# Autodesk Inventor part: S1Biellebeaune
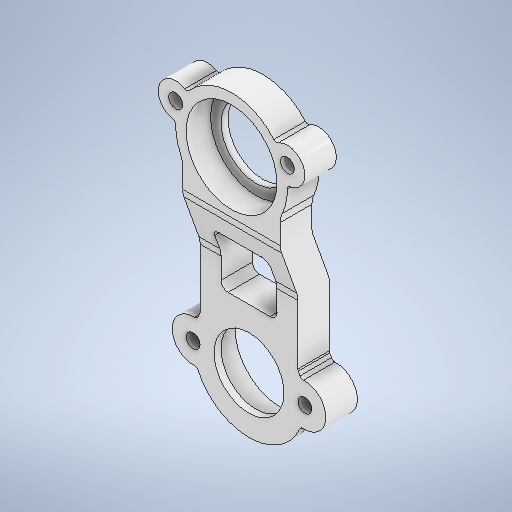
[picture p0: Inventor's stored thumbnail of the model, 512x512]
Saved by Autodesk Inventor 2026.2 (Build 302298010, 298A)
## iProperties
Created: 2026-04
Part Number: S1Biellebeaune
Material: Générique
Document SubType Name: Modeling
Designer: mel
Density: 1 g/cm^3
Appearance: Blanche
Author: mel
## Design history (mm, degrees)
sketch "Esquisse1"
  geometry: L1 (0, 0)-(-7.996, 2.998); L2 (0, -44.932)-(0, 17.591) reference; L3 (-7, -24)-(-7, -4.583); L4 (0, 0)-(7.996, 2.998); L5 (7, -24)-(7, -4.583); L6 (-3, -11.5)-(3, -11.5); L7 (4, -12.5)-(4, -18.5); L8 (3, -19.5)-(-3, -19.5); L9 (-4, -18.5)-(-4, -12.5); C1 r 1 at (-7.996, 2.998); C2 r 1 at (7.996, 2.998); C3 r 5 at (0, -28); C4 r 1 at (-8, -28); C5 r 1 at (8, -28); A1 r 2.5 centre (-7.996, 2.998) between (-6.692, 5.131) and (-8.416, 0.534); A2 r 0.5 centre (-6.431, 5.558) between (-6.692, 5.131) and (-6.053, 5.231); A3 r 0.5 centre (-8.5, 0.041) between (-8, 0.039) and (-8.416, 0.534); A4 r 5 centre (0, 0) between (0, 5) and (0, -5); A5 r 3 centre (-10, -4.583) between (-7, -4.583) and (-7.273, -3.333); A6 r 8 centre (0, 0) between (0, 8) and (-6.053, 5.231); A7 r 8 centre (0, 0) between (-8, 0.039) and (-7.273, -3.333); A8 r 2.5 centre (7.996, 2.998) between (8.416, 0.534) and (6.692, 5.131); A9 r 0.5 centre (8.5, 0.041) between (8.416, 0.534) and (8, 0.039); A10 r 8 centre (0, 0) between (7.273, -3.333) and (8, 0.039); A11 r 5 centre (0, 0) between (0, -5) and (0, 5); A12 r 3 centre (10, -4.583) between (7.273, -3.333) and (7, -4.583); A13 r 0.5 centre (6.431, 5.558) between (6.053, 5.231) and (6.692, 5.131); A14 r 8 centre (0, 0) between (6.053, 5.231) and (0, 8); A15 r 3 centre (-8, -28) between (-7.786, -25.008) and (-7.786, -30.992); A16 r 3 centre (8, -28) between (7.786, -30.992) and (7.786, -25.008); A17 r 8 centre (0, -28) between (-7.059, -24.235) and (-7.294, -24.714); A18 r 8 centre (0, -28) between (-7.294, -31.286) and (7.294, -31.286); A19 r 8 centre (0, -28) between (7.294, -24.714) and (7.059, -24.235); A20 r 0.5 centre (-7.75, -24.509) between (-7.786, -25.008) and (-7.294, -24.714); A21 r 0.5 centre (-7.5, -24) between (-7.059, -24.235) and (-7, -24); A22 r 0.5 centre (-7.75, -31.491) between (-7.294, -31.286) and (-7.786, -30.992); A23 r 0.5 centre (7.75, -31.491) between (7.786, -30.992) and (7.294, -31.286); A24 r 0.5 centre (7.75, -24.509) between (7.294, -24.714) and (7.786, -25.008); A25 r 0.5 centre (7.5, -24) between (7, -24) and (7.059, -24.235); A26 r 1 centre (-3, -12.5) between (-3, -11.5) and (-4, -12.5); A27 r 1 centre (3, -12.5) between (4, -12.5) and (3, -11.5); A28 r 1 centre (3, -18.5) between (3, -19.5) and (4, -18.5); A29 r 1 centre (-3, -18.5) between (-4, -18.5) and (-3, -19.5); 7 further points
  constraints: 61 point on circle, 34 centre point, 22 tangent, 16 end point, 14 point on line, 11 symmetric about line, 8 coincident, 8 equal radius, 2 parallel, 1 horizontal, 1 perpendicular, 8 other
  dimensions: "d1" = 2 diameter of C1; "d2" = 8.54 distance of point (0, 0) L1.end; "d3" = 69.445 deg angle of L2 L1; "d4" = 5 diameter of A1; "d5" = 1 diameter of A2; "d6" = 1 diameter of A3; "d7" = 10 diameter of A4; "d9" = 7 distance from line of point (0, 0) L3 (= 0.5 x d8); "d10" = 6 diameter of A5; "d11" = 10 horizontal distance of point (0, 0) A5.centre; "d13" = 28 distance of C3.centre point (0, 0); "d17" = 6 diameter of A15; "d18" = 8 distance of C3.centre A15.centre; "d19" = 2 diameter of C4 (= d1); "d20" = 2 diameter of C5 (= d19); "d21" = 0.5 radius of A20; "d22" = 8 distance of point (4, -19.5) point (-4, -19.5); "d23" = 3 distance between parallel lines of L9 L3; "d24" = 11.5 distance from line of point (0, 0) L6; "d25" = 8.5 distance from line of C3.centre L8; "d26" = 10 diameter of C3 (= d7); "d47" = 1 radius of A26
extrude "Extrusion1" new body sketch "Esquisse1" distance "d27" = 7; taper "d28" = 0 deg
sketch "Esquisse3"
  geometry: L1 (-4.583, 7)-(-24, 7) reference; L2 (-18.5, 0)-(-12.5, 0) reference; L3 (-36, 0)-(-36, 7) reference; L4 (8, 0)-(8, 7) reference; L5 (8, 7)-(5.231, 7) reference; L6 (-31.286, 0)-(-36, 0) reference; L7 (-14.511, 0.175)-(-8.489, 2.325); L8 (-8.489, 6.825)-(-14.511, 4.675); L9 (-31.286, 7)-(-36, 7) reference; L10 (-36, 7)-(-15.52, 7); L11 (-15.52, 4.5)-(-36, 4.5); L12 (-36, 4.5)-(-36, 7); L13 (8, 0)-(5.231, 0) reference; L14 (8, 0)-(-15.52, 0); L15 (-7.48, 2.5)-(8, 2.5); L16 (8, 2.5)-(8, 0); A1 r 3 centre (-7.48, -0.5) between (-7.48, 2.5) and (-8.489, 2.325); A2 r 3 centre (-7.48, 4) between (-7.48, 7) and (-8.489, 6.825); A3 r 3 centre (-15.52, 7.5) between (-15.52, 4.5) and (-14.511, 4.675); A4 r 3 centre (-15.52, 3) between (-15.52, 0) and (-14.511, 0.175); 9 further points
  constraints: 16 end point, 8 point on circle, 8 tangent, 4 centre point, 2 horizontal, 2 parallel, 2 point on line
  dimensions: "d29" = 20.48 distance from line of A4.centre L3; "d30" = 20.48 distance from line of L3 A3.centre (= d29); "d31" = 6 diameter of A4; "d32" = 6 diameter of A3 (= d31); "d33" = 6 diameter of A1 (= d31); "d34" = 6 diameter of A2 (= d31); "d35" = 15.48 distance from line of A2.centre L4; "d36" = 15.48 distance from line of L4 A1.centre (= d35); "d37" = 7.5 distance from line of A1.centre L5; "d38" = 7.5 distance from line of A3.centre L6 (= d37)
extrude "Extrusion2" cut sketch "Esquisse3" extent not by distance; stored distance "d39" = 0; taper "d40" = 0 deg
sketch "Esquisse6"
  geometry: C1 r 6.5 at (0, 0); 1 further point
  constraints: 1 centre point, 1 coincident
  dimensions: "d48" = 13 diameter of C1
extrude "Extrusion5" cut sketch "Esquisse6" distance "d49" = 3.5; taper "d50" = 0 deg
sketch "Esquisse7"
  geometry: C1 r 5 at (0, -28) reference; C2 r 6.5 at (0, -28); 1 further point
  constraints: 1 centre point, 1 coincident
  dimensions: "d51" = 13 diameter of C2
extrude "Extrusion6" cut sketch "Esquisse7" distance "d52" = 3.5; taper "d53" = 0 deg
feature "Filetage3" dims "d58" = 4, "d59" = 0
feature "Filetage4" dims "d60" = 4, "d61" = 0
feature "Filetage5" dims "d62" = 4, "d63" = 0
feature "Filetage6" dims "d64" = 4, "d65" = 0
node "Solide1"
other parameters: "d0" = 16, "d8" = 14, "d14" = 16
